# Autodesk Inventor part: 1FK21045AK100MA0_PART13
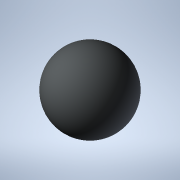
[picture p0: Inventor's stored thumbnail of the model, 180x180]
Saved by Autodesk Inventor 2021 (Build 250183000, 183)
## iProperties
Created: 2025-04
Part Number: 1FK21045AK100MA0_PART13
Material: Generic
Catalog Web Link: www.3dfindit.com
Description: -Servo synchronous motor
Document SubType Name: Modeling
Designer: psAdmin
Mass: 0.137258 g
Surface Area: 1.2868 cm^2
Volume: 0.137258 cm^3
Density: 1 g/cm^3
Appearance: PSOLRGB-212-217-219
Category: PARTsolutions
Title: 1FK21045AK100MA0_PART13
Author: Cadenas PARTsolutions
Comments: Servo synchronous motor
Sending System: PARTsolutions
Preprocessor: ST-DEVELOPER v19.3
PSOL_IDENT_0: {$CADENAS_DATA/23d-libs/siemens_ag/_cat_/e0/5f/1fk21045ak100ma0.prj},216 {VTYP=3D},{NB=1FK21045AK100
PSOL_IDENT_1: MA0_PART13},{LINA=1FK21045AK100MA0_PART13},{NN=1FK21045AK100MA0_PART13},{NOPRJ=TRUE},{DATE=19.08.202
PSOL_IDENT_2: 5 14:01:03},{GEOMDATE=30.07.2025 02:01:57},{VERSION=},{LINEID=10},{WBVAR=},{WBNUMERIC=}  {NB=1FK2104
PSOL_IDENT_3: 5AK100MA0_PART13},{LINA=1FK21045AK100MA0_PART13},{KT=DUMMY},{PREVIEW=../../../_pool_/0f/2c/p_d211_xx
PSOL_IDENT_4: _00438j.png},{DESCSHORT=SIMOTICS S-1FK2 HD, SINAMICS S210 3AC 400V-480V, 1.7 Nm, 6000 rpm},{DESCLONG=
PSOL_IDENT_5: SIMOTICS S-1FK2 HD servo motor M0=2.4 Nm; PN = 1.07 kW at nN=6000 rpm (380-480 V); PN = 0.75 kW at n
PSOL_IDENT_6: N=3000 rpm (200-240 V); with holding brake; degree of protection IP64; cylindrical shaft D19x40mm; a
PSOL_IDENT_7: bsolute encoder 22-bit + 12-bit multiturn (encoder AM22DQC); with OCC interface; plug size M17, rota
PSOL_IDENT_8: table; SIMOTICS S-1FK2 servomotorfor a wide range of uses in industrial environments. SIMOTICS S‑1FK
PSOL_IDENT_9: 2 servomotors are compact synchronous motors with a high dynamic performance that set themselves apa
PSOL_IDENT_10: rt as a result of their high power density, degree of protection and overload capability. The motors
PSOL_IDENT_11: are available in two variants: as High Dynamic variant (highest dynamic performance as a result of
PSOL_IDENT_12: the low intrinsic moment of inertia for applications demanding a high dynamic performance with low m
PSOL_IDENT_13: oved masses) - and as Compact variant (precise and stable closed-loop control for medium up to large
PSOL_IDENT_14: moved masses as a result of a medium intrinsic moment of inertia). SIMOTICSS‑1FK2 servomotors fully
PSOL_IDENT_15: exploit their strengths in a system with the SINAMICSS210 frequency converter and simple connection
PSOL_IDENT_16: using the one cable connection (OCC). Advantages include the short control and positioning times, f
PSOL_IDENT_17: ast and precise correction of disturbing quantities as well as stable control with a high dynamic pe
PSOL_IDENT_18: rformance. The servo motors can be configured to address a wide range of requirements. For example w
PSOL_IDENT_19: ith and without holding brake, IP64 or IP65 degree of protection, singleturn or multiturn absolute e
PSOL_IDENT_20: ncoders - to name just a few. Further, the servomotors are available in different shaft heights exte
PSOL_IDENT_21: nding from 20 to 100. A shaft sealing ring is available to achieve an IP65 degree of protection and
PSOL_IDENT_22: for subsequent mounting at the motor or as spare part. SIMOTICS - the optimum motor for each and eve
PSOL_IDENT_23: ry motion control application.},{INTNO=804766807114},{SUPPLIERALTNO=1FK2104-5AK10-0MA0},{MANUID=1FK2
PSOL_IDENT_24: 1045AK100MA0},{MANUNAME=Siemens},{MANUTYPEDESC=Synchronous motor 1FK2-HD 2,39 Nm},{AAU732=SIMOTICS},
PSOL_IDENT_25: {AAO057=S-1FK2},{AAU734=SIMOTICS S-1FK2 HD servo motor M0=2.4 Nm; PN = 1.07 kW at nN=6000 rpm (380-4
PSOL_IDENT_26: 80 V); PN = 0.75 kW at nN=3000 rpm (200-240 V); with holding brake; degree of protection IP64; cylin
PSOL_IDENT_27: drical shaft D19x40mm; absolute encoder 22-bit + 12-bit multiturn (encoder AM22DQC); with OCC interf
PSOL_IDENT_28: ace; plug size M17, rotatable;},{AAW338=Synchronous motor 1FK2-HD 2,39 Nm},{AAO742=SIMOTICS},{AAO663=
PSOL_IDENT_29: 4042948691236},{NOCUPEROU=1},{PRICEQUANTITY=1},{QUANTITYMIN=1},{QUANTITYINT=1},{CTN=85015100},{COO=D
PSOL_IDENT_30: E},{AAO676=1FK2104-5AK10-0MA0},{AAO677=Siemens AG},{ORDERUNIT=C62},{CONTENTUNIT=C62}
NB: 1FK21045AK100MA0_PART13
NT: Servo synchronous motor
NBSYN: $MANUID._PART13
LINA: 1FK21045AK100MA0_PART13
CATALOG: SIEMENS
PREVIEW: ../../../_pool_/0f/2c/p_d211_xx_00438j.png
DESCSHORT: SIMOTICS S-1FK2 HD, SINAMICS S210 3AC 400V-480V, 1.7 Nm, 6000 rpm
DESCLONG: SIMOTICS S-1FK2 HD servo motor M0=2.4 Nm; PN = 1.07 kW at nN=6000 rpm (380-480 V); PN = 0.75 kW at nN=3000 rpm (200-240 V); with holding brake; degree of protec
INTNO: 804766807114
SUPPLIERALTNO: 1FK2104-5AK10-0MA0
MANUID: 1FK21045AK100MA0
MANUNAME: Siemens
MANUTYPEDESC: Synchronous motor 1FK2-HD 2,39 Nm
AAU732: SIMOTICS
AAO057: S-1FK2
AAU734: SIMOTICS S-1FK2 HD servo motor M0=2.4 Nm; PN = 1.07 kW at nN=6000 rpm (380-480 V); PN = 0.75 kW at nN=3000 rpm (200-240 V); with holding brake; degree of protec
AAW338: Synchronous motor 1FK2-HD 2,39 Nm
AAO742: SIMOTICS
AAO663: 4042948691236.0
NOCUPEROU: 1
PRICEQUANTITY: 1
QUANTITYMIN: 1
QUANTITYINT: 1
CTN: 85015100
COO: DE
ARTICLENO: 1FK21045AK100MA0_PART13
BOMINFO: 1FK21045AK100MA0_PART13
CREATOR: CADENAS GmbH
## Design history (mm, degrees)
feature "2025_04_17_15_45_15_0090"
body "Solid1"
